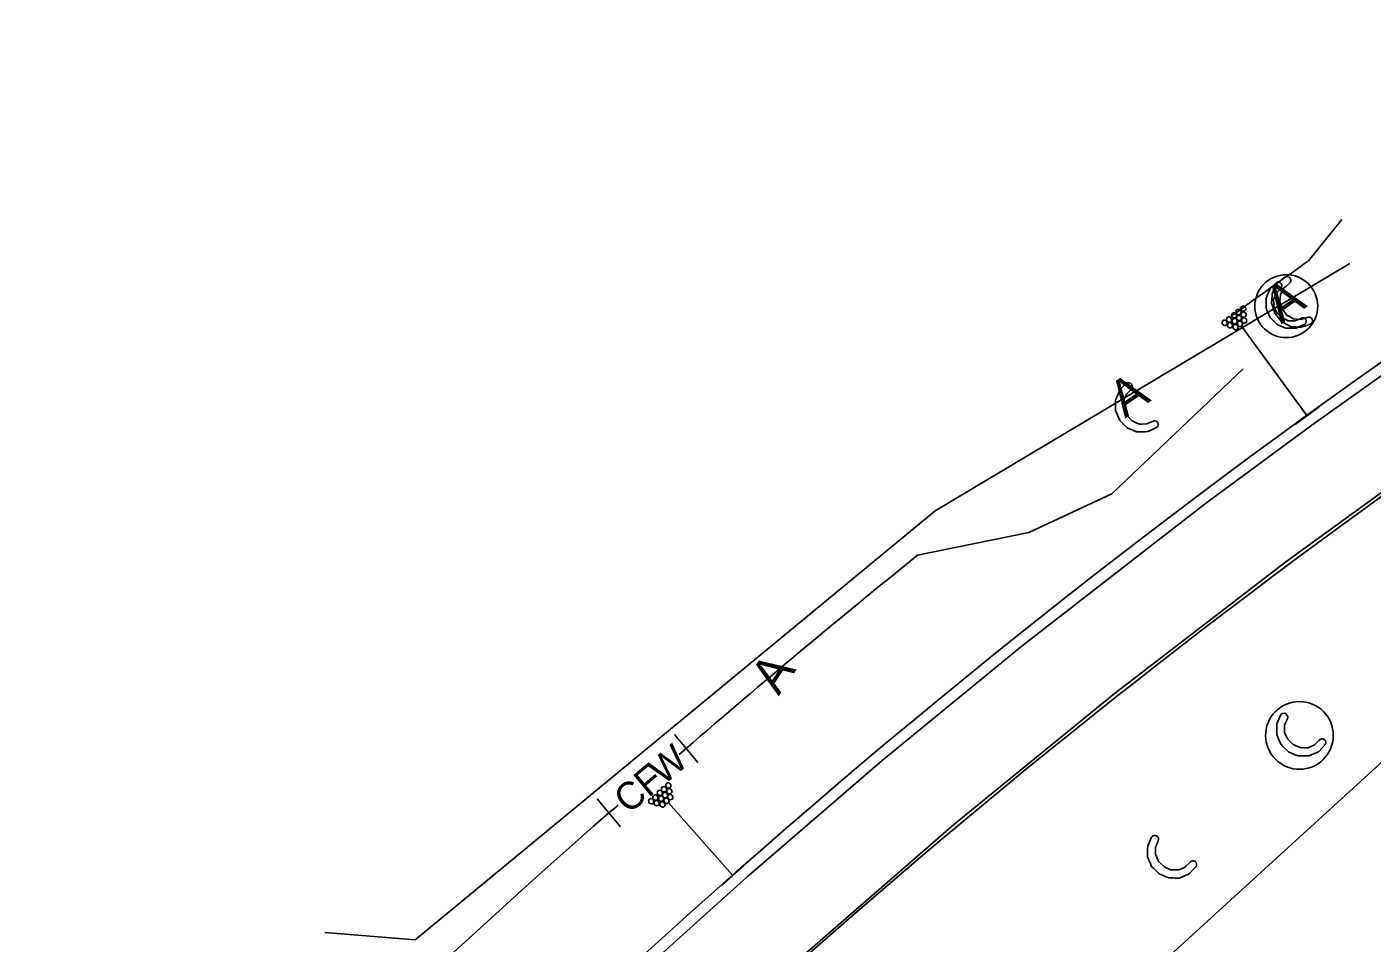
# Model space of a CAD drawing. Extents: x 2357856 to 2382083, y 331121 to 347536.
# Drawn here: x 2380554 to 2380922.9, y 332728.7 to 332979.9 of the extents above; entities that cross this region are included whole.
import ezdxf

# ---------------------------------------------------------------- set-up
doc = ezdxf.new("R2010")
doc.units = 0
for name, color, linetype in [('Coir Fiber Wattle Both CELL', 7, 'Continuous'), ('EC Title Sheet CELL', 7, 'Continuous'), ('Matting and PSRM Summary Sheet CELL', 7, 'Continuous'), ('Old_Level_12', 7, 'Continuous'), ('P_NCDOT_Horizontal_Alignment_Station_Label', 7, 'Continuous'), ('P_NCDOT_Horizontal_Alignment_Tick_Small', 7, 'Continuous'), ('Prop North Arrow for Plan Sheets CELL', 7, 'Continuous'), ('Sheet Data Field CELL', 7, 'Continuous'), ('Sheet_Named_Boundary', 7, 'Continuous'), ('Sheet_Title_CELL', 7, 'Continuous')]:
    doc.layers.add(name, color=color, linetype=linetype)

# ---------------------------------------------------------------- blocks, each defined once
blk = doc.blocks.new('WATTLECG')
at = {"layer": 'Prop North Arrow for Plan Sheets CELL'}
for p, q in [((-0.0218, 0.0365), (-0.0208, 0.0381)), ((-0.0111, 0.0445), (-0.0208, 0.0381)), ((-0.0037, 0.0494), (-0.0111, 0.0445)), ((0.0025, 0.0505), (-0.0037, 0.0494)), ((0.0147, 0.0527), (0.0025, 0.0505)), ((-0.0315, 0.0209), (-0.0352, 0.0002)), ((-0.0352, 0.0001), (-0.0352, 0.0002)), ((-0.0352, 0.0001), (-0.0318, -0.02)), ((-0.0315, 0.0209), (-0.0265, 0.029)), ((-0.0218, 0.0365), (-0.0265, 0.029)), ((-0.0318, -0.02), (-0.0267, -0.0281)), ((-0.0267, -0.0281), (-0.0206, -0.038)), ((-0.0206, -0.038), (-0.0137, -0.0424)), ((-0.0137, -0.0424), (-0.0037, -0.0488)), ((-0.0011, -0.0493), (-0.0037, -0.0488)), ((-0.0011, -0.0493), (0.0135, -0.0521))]:
    blk.add_line(p, q, dxfattribs=at)
blk.add_lwpolyline([(0.0135, -0.0729), (0.0012, -0.0707), (-0.0131, -0.0682), (-0.0187, -0.0646), (-0.0255, -0.0603), (-0.0376, -0.0526), (-0.0378, -0.0523), (-0.0397, -0.0493), (-0.0401, -0.0488), (-0.0443, -0.0424), (-0.0472, -0.038), (-0.0536, -0.0281), (-0.0551, -0.02), (-0.0589, 0.0001), (-0.0589, 0.0002), (-0.055, 0.0209), (-0.0534, 0.029), (-0.0484, 0.0365), (-0.0474, 0.0381), (-0.0431, 0.0445), (-0.0399, 0.0494), (-0.0391, 0.0505), (-0.0375, 0.053), (-0.0375, 0.053), (-0.0273, 0.0596), (-0.0183, 0.0654), (-0.0128, 0.0689), (0.0009, 0.0716), (0.0131, 0.0739)], dxfattribs=at)
for centre, radius, start in [((0.0131, 0.0633), 0.0107, 278.8874), ((0.0135, -0.0625), 0.0104, 270)]:
    blk.add_arc(centre, radius, start, 90, dxfattribs=at)
blk = doc.blocks.new('WATTLEWITHPAMCG')
at = {"layer": 'Prop North Arrow for Plan Sheets CELL'}
for p, q in [((-0.00231, 0.00928), (-0.00432, 0.00794)), ((-0.00077, 0.01029), (-0.00231, 0.00928)), ((0.00052, 0.01053), (-0.00077, 0.01029)), ((0.00307, 0.01098), (0.00052, 0.01053)), ((-0.00656, 0.00435), (-0.00733, 0.00004)), ((-0.00733, 0.00002), (-0.00733, 0.00004)), ((-0.00733, 0.00002), (-0.00662, -0.00416)), ((-0.00656, 0.00435), (-0.00551, 0.00604)), ((-0.00453, 0.00761), (-0.00551, 0.00604)), ((-0.00453, 0.00761), (-0.00432, 0.00794)), ((-0.00662, -0.00416), (-0.00556, -0.00586)), ((-0.00556, -0.00586), (-0.00429, -0.00791)), ((-0.00429, -0.00791), (-0.00285, -0.00884)), ((-0.00285, -0.00884), (-0.00077, -0.01017)), ((-0.00023, -0.01028), (-0.00077, -0.01017)), ((-0.00023, -0.01028), (0.00282, -0.01086))]:
    blk.add_line(p, q, dxfattribs=at)
blk.add_lwpolyline([(0.00282, -0.01518), (0.00026, -0.01474), (-0.00272, -0.01422), (-0.0039, -0.01347), (-0.00532, -0.01256), (-0.00784, -0.01095), (-0.00788, -0.01089), (-0.00828, -0.01028), (-0.00835, -0.01017), (-0.00922, -0.00884), (-0.00983, -0.00791), (-0.01116, -0.00586), (-0.01149, -0.00416), (-0.01228, 0.00002), (-0.01228, 0.00004), (-0.01146, 0.00435), (-0.01113, 0.00604), (-0.01009, 0.00761), (-0.00987, 0.00794), (-0.00899, 0.00928), (-0.00832, 0.01029), (-0.00816, 0.01053), (-0.00782, 0.01104), (-0.00781, 0.01105), (-0.00569, 0.01241), (-0.00381, 0.01362), (-0.00268, 0.01435), (0.0002, 0.01491), (0.00273, 0.01541)], dxfattribs=at)
for centre, radius, start, end in [((-0.00028, 0.00022), 0.01916, 90, 180), ((-0.00028, 0.00022), 0.01916, 0, 90), ((0.00273, 0.01318), 0.00222, 278.88736, 90), ((-0.00028, 0.00022), 0.01916, 180, 270), ((-0.00028, 0.00022), 0.01916, 270, 360), ((0.00282, -0.01302), 0.00216, 270, 90)]:
    blk.add_arc(centre, radius, start, end, dxfattribs=at)
at = {"layer": 'Prop North Arrow for Plan Sheets CELL', "xscale": 0.20833333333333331, "yscale": 0.20833333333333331}
blk.add_blockref('WATTLECG', (0, 0), dxfattribs=at)

msp = doc.modelspace()

# ---------------------------------------------------------------- linework, layer by layer
at = {"layer": 'Coir Fiber Wattle Both CELL'}
for radius, start, end in [(2080, 122.68319, 138.66863), (2050, 124.90194, 138.73574)]:
    msp.add_arc((2382124.62, 331188.54), radius, start, end, dxfattribs=at)
at = {"layer": 'EC Title Sheet CELL'}
msp.add_lwpolyline([(2380916.74, 332915.07), (2380803.03, 332847.21), (2380660.48, 332729.65), (2380635.69, 332731.65)], dxfattribs=at)
at = {"layer": 'Matting and PSRM Summary Sheet CELL'}
for p, q in [((2380734.74, 332782.08), (2380731.54, 332785.92)), ((2380732.82, 332780.48), (2380734.74, 332782.08)), ((2380734.74, 332782.08), (2380737.94, 332778.24)), ((2380713.54, 332764.43), (2380710.34, 332768.27)), ((2380713.54, 332764.43), (2380715.46, 332766.03)), ((2380714.16, 332764.92), (2380716.08, 332766.52)), ((2380713.54, 332764.43), (2380716.74, 332760.59))]:
    msp.add_line(p, q, dxfattribs=at)
at = {"layer": 'Old_Level_12'}
for p, q in [((2380887.08, 332897.92), (2380904.97, 332873.43)), ((2380908.4, 332875.75), (2380901.8, 332870.95)), ((2380729.88, 332767.18), (2380747.51, 332747.38)), ((2380750.71, 332750.03), (2380744.6, 332744.61))]:
    msp.add_line(p, q, dxfattribs=at)
for centre, major_axis in [((2380886.25, 332901.74), (0.441, -0.605)), ((2380887.53, 332902.68), (0.441, -0.605)), ((2380882.44, 332898.8), (0.441, -0.605)), ((2380883.67, 332899.7), (0.441, -0.605)), ((2380883.89, 332898.15), (0.441, -0.605)), ((2380885.02, 332900.85), (0.441, -0.605)), ((2380885.19, 332899.26), (0.441, -0.605)), ((2380885.4, 332897.63), (0.441, -0.605)), ((2380886.37, 332900.13), (0.441, -0.605)), ((2380886.63, 332898.53), (0.441, -0.605)), ((2380887.65, 332901.06), (0.441, -0.605)), ((2380887.78, 332899.44), (0.441, -0.605)), ((2380726.32, 332768.62), (0.498, -0.56)), ((2380727.55, 332769.9), (0.498, -0.56)), ((2380727.88, 332768.34), (0.498, -0.56)), ((2380728.69, 332770.91), (0.498, -0.56)), ((2380728.97, 332769.31), (0.498, -0.56)), ((2380729.88, 332771.96), (0.498, -0.56)), ((2380730.16, 332770.36), (0.498, -0.56)), ((2380730.43, 332768.76), (0.498, -0.56)), ((2380725.18, 332767.61), (0.498, -0.56)), ((2380726.69, 332767.11), (0.498, -0.56)), ((2380728.25, 332766.73), (0.498, -0.56)), ((2380729.38, 332767.74), (0.498, -0.56))]:
    msp.add_ellipse(centre, major_axis=major_axis, ratio=0.927398, dxfattribs=at)
at = {"layer": 'P_NCDOT_Horizontal_Alignment_Station_Label'}
for p, q in [((2380899.14, 332789.08), (2380898.89, 332788.5)), ((2380898.89, 332788.5), (2380898.89, 332787.61)), ((2380898.89, 332787.61), (2380898.89, 332786.45)), ((2380899.64, 332790.22), (2380899.14, 332789.08)), ((2380898.96, 332786.28), (2380898.89, 332786.45)), ((2380898.96, 332786.28), (2380899.33, 332785.47)), ((2380899.73, 332784.61), (2380899.33, 332785.47)), ((2380899.73, 332784.61), (2380901.25, 332783.15)), ((2380907.26, 332783.25), (2380908.3, 332784.31)), ((2380901.26, 332783.15), (2380901.25, 332783.15)), ((2380901.26, 332783.15), (2380903.11, 332782.32)), ((2380903.11, 332782.32), (2380904.08, 332782.29)), ((2380904.08, 332782.29), (2380905.23, 332782.25)), ((2380905.23, 332782.25), (2380905.98, 332782.58)), ((2380905.98, 332782.58), (2380907.07, 332783.06)), ((2380907.26, 332783.25), (2380907.07, 332783.06)), ((2380863.54, 332752.82), (2380863.46, 332752.99)), ((2380864.3, 332751.14), (2380863.9, 332752.01)), ((2380865.83, 332749.68), (2380865.82, 332749.69)), ((2380871.83, 332749.78), (2380871.64, 332749.59))]:
    msp.add_line(p, q, dxfattribs=at)
for points in [[(2380910.03, 332783.16), (2380909.17, 332782.25), (2380908.17, 332781.2), (2380907.56, 332780.93), (2380906.81, 332780.6), (2380905.5, 332780.03), (2380905.47, 332780.03), (2380905.12, 332780.03), (2380905.06, 332780.03), (2380904.29, 332780.04), (2380903.76, 332780.04), (2380902.59, 332780.05), (2380901.82, 332780.37), (2380899.94, 332781.17), (2380899.93, 332781.17), (2380898.42, 332782.65), (2380897.84, 332783.23), (2380897.49, 332784.06), (2380897.41, 332784.24), (2380897.11, 332784.94), (2380896.89, 332785.48), (2380896.83, 332785.61), (2380896.72, 332785.88), (2380896.72, 332785.89), (2380896.74, 332787.1), (2380896.75, 332788.17), (2380896.76, 332788.82), (2380897.3, 332790.11), (2380897.78, 332791.26)], [(2380862.35, 332757.8), (2380861.88, 332756.65), (2380861.33, 332755.35), (2380861.32, 332754.71), (2380861.31, 332753.63), (2380861.29, 332752.43), (2380861.29, 332752.42), (2380861.41, 332752.15), (2380861.46, 332752.02), (2380861.68, 332751.48), (2380861.98, 332750.77), (2380862.06, 332750.6), (2380862.41, 332749.76), (2380863, 332749.19), (2380864.5, 332747.71), (2380864.51, 332747.71), (2380866.39, 332746.91), (2380867.16, 332746.59), (2380868.33, 332746.58), (2380868.86, 332746.57), (2380869.63, 332746.57), (2380869.69, 332746.57), (2380870.04, 332746.56), (2380870.07, 332746.56), (2380871.39, 332747.14), (2380872.13, 332747.47), (2380872.74, 332747.74), (2380873.74, 332748.79), (2380874.6, 332749.7)], [(2380872.87, 332750.85), (2380871.83, 332749.78), (2380871.64, 332749.59), (2380870.56, 332749.12), (2380869.8, 332748.79), (2380868.65, 332748.83), (2380867.69, 332748.86), (2380865.83, 332749.68), (2380865.82, 332749.69), (2380864.3, 332751.14), (2380863.9, 332752.01), (2380863.54, 332752.82), (2380863.46, 332752.99), (2380863.46, 332754.15), (2380863.46, 332755.04), (2380863.71, 332755.62), (2380864.21, 332756.76), (2380864.21, 332756.76)]]:
    msp.add_lwpolyline(points, dxfattribs=at)
for centre, radius, start, end in [((2380902.95, 332785.67), 9.29, 56.361, 146.361), ((2380898.67, 332790.67), 1.07, 335.2483, 146.361), ((2380902.95, 332785.67), 9.29, 326.361, 56.361), ((2380902.95, 332785.67), 9.29, 146.361, 236.361), ((2380909.16, 332783.73), 1.04, 326.361, 146.361), ((2380902.95, 332785.67), 9.29, 236.361, 326.361), ((2380863.24, 332757.2), 1.07, 335.2483, 146.361), ((2380873.73, 332750.27), 1.04, 326.361, 146.361)]:
    msp.add_arc(centre, radius, start, end, dxfattribs=at)
at = {"layer": 'Sheet Data Field CELL'}
for points in [[(2381104.38, 332997.7), (2381069.47, 332977.56), (2381040.56, 332960.19), (2381010.45, 332941.41), (2380956.28, 332905.78), (2380930.1, 332887.68), (2380906.38, 332870.75), (2380877.19, 332849.22), (2380826.88, 332810.21), (2380788.53, 332778.76), (2380751.41, 332746.82), (2380717.5, 332716.27), (2380671.02, 332672.12), (2380634.87, 332635.81), (2380609.99, 332609.75), (2380552.58, 332545.97)], [(2380531.76, 332468.65), (2380565, 332507.19), (2380582.89, 332541.2), (2380648.52, 332612.53), (2380680.76, 332645.21), (2380717.67, 332680.89), (2380747.68, 332708.62), (2380808.05, 332761.2), (2380852.12, 332797.07), (2380899.23, 332833.24), (2380937.38, 332860.99), (2380975.7, 332887.54), (2381012.85, 332912.08), (2381058.61, 332940.75), (2381095.37, 332962.59), (2381137.68, 332988.81)]]:
    msp.add_lwpolyline(points, dxfattribs=at)
at = {"layer": 'Sheet_Named_Boundary'}
for p, q in [((2380914.59, 332927.1), (2380905.41, 332915.77)), ((2380798.22, 332835.05), (2380828.77, 332841.27)), ((2380822.55, 332684.46), (2380949.84, 332800.56))]:
    msp.add_line(p, q, dxfattribs=at)
msp.add_lwpolyline([(2380887.51, 332886.2), (2380851.47, 332851.94), (2380828.77, 332841.27)], dxfattribs=at)
for centre, radius, start, end in [((2382262.22, 330998.25), 2349, 125.28287, 125.9062), ((2382271.03, 331005.44), 2348.76, 128.83379, 130.85061), ((2382262.22, 330998.25), 2349, 131.24605, 135.58734)]:
    msp.add_arc(centre, radius, start, end, dxfattribs=at)
at = {"layer": 'Sheet_Title_CELL'}
for p, q in [((2380897.72, 332906.39), (2380897.74, 332906.58)), ((2380897.61, 332904.55), (2380897.67, 332905.5)), ((2380898.27, 332902.54), (2380898.27, 332902.55)), ((2380903.61, 332899.81), (2380903.36, 332899.73))]:
    msp.add_line(p, q, dxfattribs=at)
for points in [[(2380899.02, 332911.34), (2380898.06, 332910.55), (2380896.97, 332909.66), (2380896.66, 332909.09), (2380896.14, 332908.15), (2380895.56, 332907.1), (2380895.55, 332907.09), (2380895.53, 332906.8), (2380895.51, 332906.66), (2380895.46, 332906.08), (2380895.39, 332905.31), (2380895.37, 332905.12), (2380895.29, 332904.22), (2380895.54, 332903.44), (2380896.18, 332901.42), (2380896.18, 332901.42), (2380897.46, 332899.83), (2380897.99, 332899.19), (2380899.02, 332898.63), (2380899.49, 332898.37), (2380900.16, 332898.01), (2380900.21, 332897.98), (2380900.52, 332897.81), (2380900.55, 332897.79), (2380901.98, 332897.69), (2380902.79, 332897.63), (2380903.46, 332897.58), (2380904.84, 332898.04), (2380906.02, 332898.43)], [(2380905.03, 332900.26), (2380903.61, 332899.81), (2380903.36, 332899.73), (2380902.18, 332899.82), (2380901.36, 332899.89), (2380900.36, 332900.46), (2380899.52, 332900.94), (2380898.27, 332902.54), (2380898.27, 332902.55), (2380897.61, 332904.55), (2380897.67, 332905.5), (2380897.72, 332906.39), (2380897.74, 332906.58), (2380898.28, 332907.6), (2380898.7, 332908.38), (2380899.2, 332908.77), (2380900.17, 332909.55), (2380900.17, 332909.55)]]:
    msp.add_lwpolyline(points, dxfattribs=at)
for centre, radius, start in [((2380899.52, 332910.4), 1.07, 307.2039), ((2380905.53, 332899.34), 1.04, 298.3166)]:
    msp.add_arc(centre, radius, start, 118.3166, dxfattribs=at)

# ---------------------------------------------------------------- block references
at = {"layer": 'EC Title Sheet CELL', "xscale": 100, "yscale": 100, "rotation": 34.28060849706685}
msp.add_blockref('WATTLECG', (2380858.57, 332875.33), dxfattribs=at)
at = {"layer": 'Prop North Arrow for Plan Sheets CELL', "xscale": 450.00000000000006, "yscale": 450.00000000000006, "rotation": 34.28060849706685}
msp.add_blockref('WATTLEWITHPAMCG', (2380899.49, 332903.35), dxfattribs=at)

# ---------------------------------------------------------------- texts
at = {"layer": 'Matting and PSRM Summary Sheet CELL'}
for s, p in [('W', (2380728.48, 332771.83)), ('F', (2380724.45, 332768.49)), ('C', (2380718.96, 332763.92))]:
    msp.add_text(s, height=7.54, rotation=39.781, dxfattribs=at).set_placement(p)
at = {"layer": 'P_NCDOT_Horizontal_Alignment_Tick_Small'}
for rotation, p in [(34.2806, (2380897.93, 332898.35)), (34.2806, (2380855.12, 332872.52)), (56.361, (2380760.14, 332796.35))]:
    msp.add_text('A', height=10, rotation=rotation, dxfattribs=at).set_placement(p)

doc.saveas('drawing.dxf')
